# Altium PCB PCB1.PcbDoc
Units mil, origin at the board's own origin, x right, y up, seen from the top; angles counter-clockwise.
Board outline 6299.21 x 3937.01 mil, 4 copper layers (Top Layer, Top Inner, Bottom Inner, Bottom Layer), stack 60.709 mil thick; 67 components, 52 nets, 221 pads, 71 vias.
Unrouted connection lines stored in the file: 34.
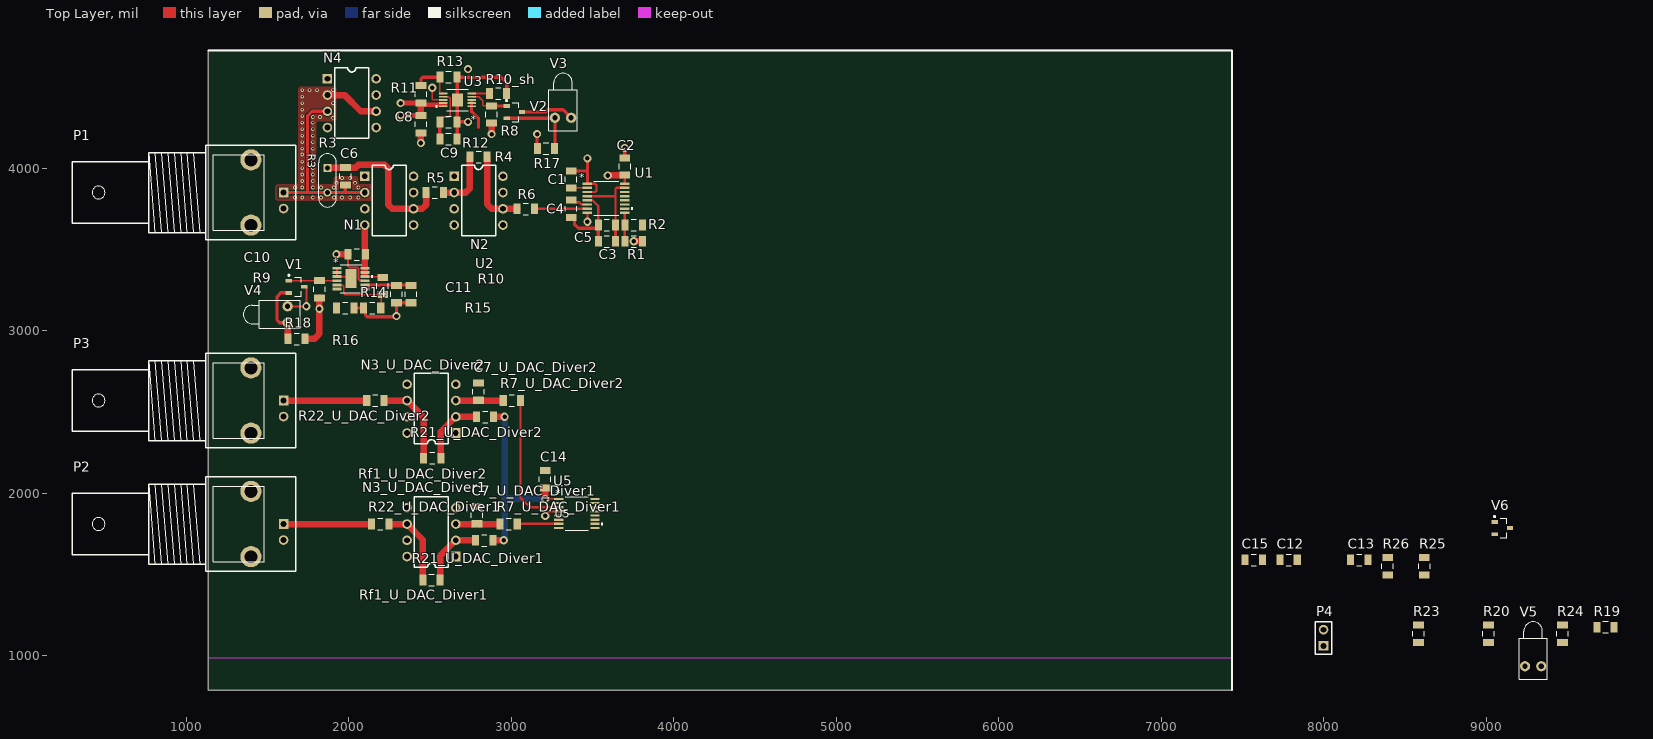
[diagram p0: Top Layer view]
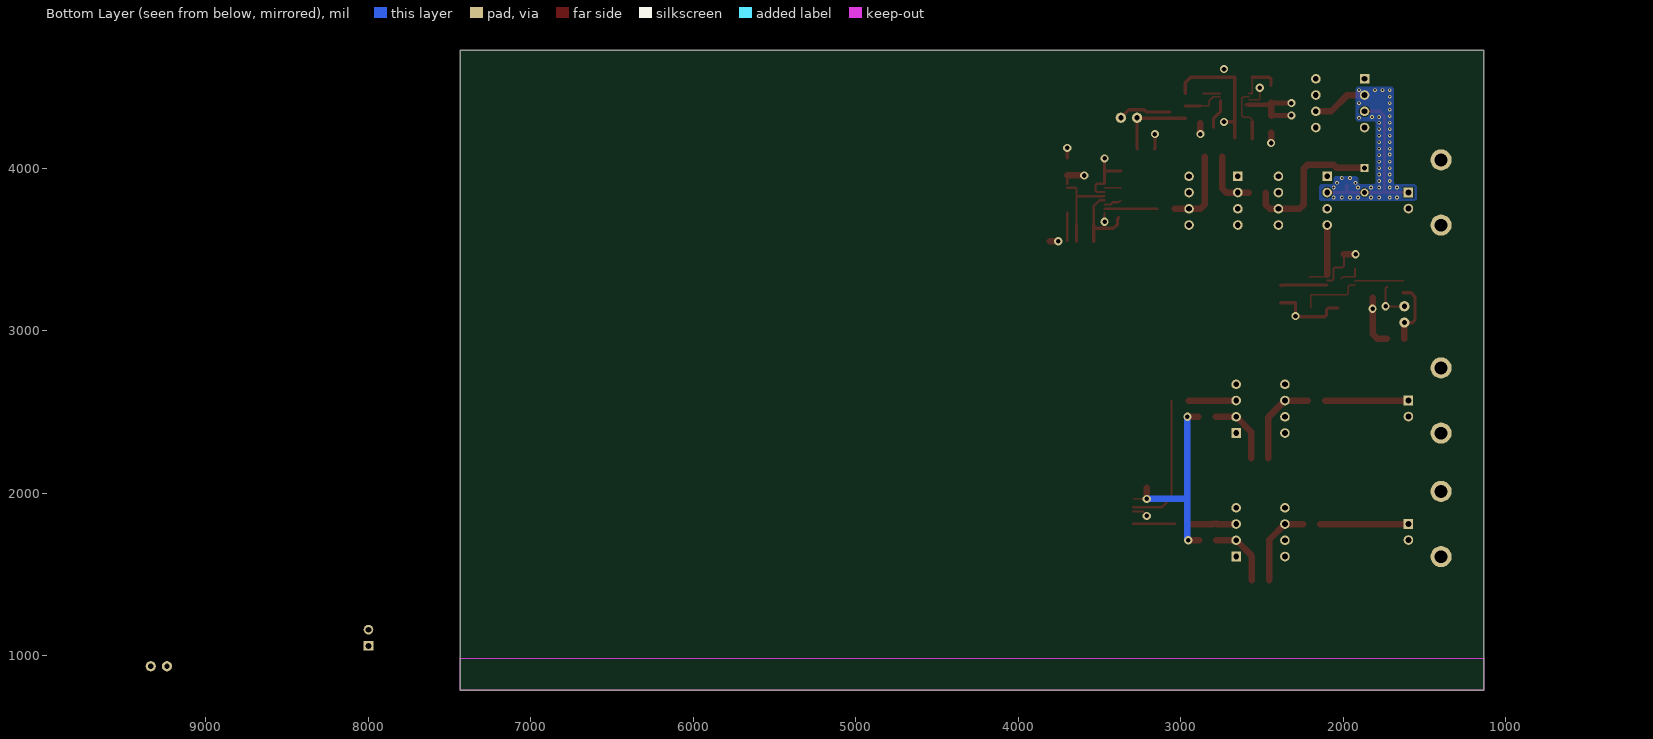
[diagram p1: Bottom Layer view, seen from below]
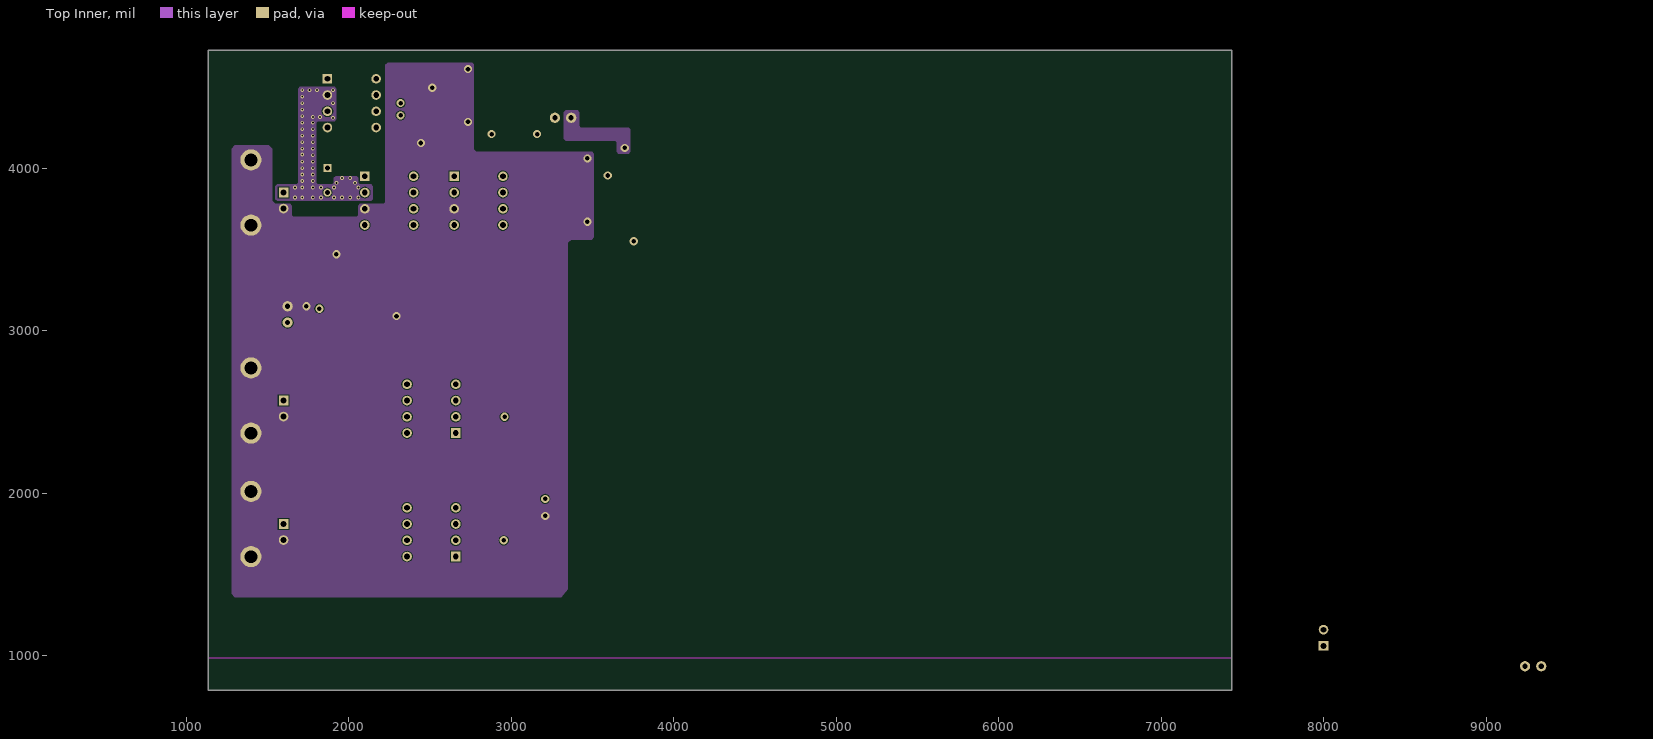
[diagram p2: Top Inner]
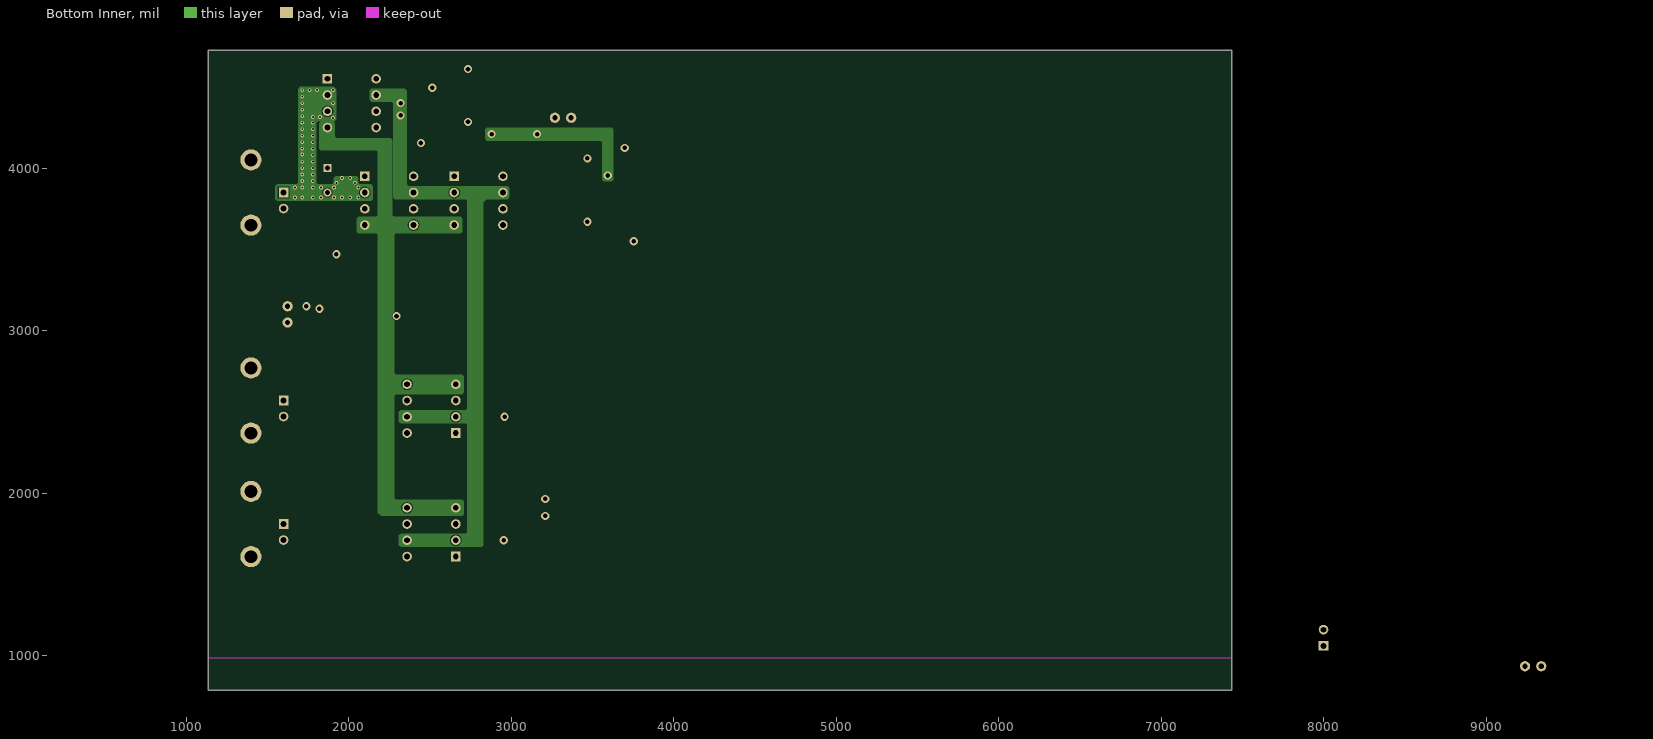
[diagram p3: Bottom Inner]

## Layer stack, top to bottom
Top Solder: solder mask 0.9843, Solder Resist, Dk 3.5
Top Layer: signal copper 1.378
Dielectric 1: prepreg 5.3543, PP-006, Dk 4.5
Top Inner: signal copper 1.378
Dielectric 2: dielectric 44.4882, FR-4, Dk 4.5
Bottom Inner: signal copper 1.378
Dielectric 3: prepreg 5.3543, PP-006, Dk 4.5
Bottom Layer: signal copper 1.378
Bottom Solder: solder mask 0.9843, Solder Resist, Dk 3.5

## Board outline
1137.4,787.4 7436.61,787.4 7436.61,4724.41 1137.4,4724.41

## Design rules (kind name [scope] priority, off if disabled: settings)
Clearance Clearance_1 [All] p1: gap=5 ignorepadtopadclearanceinfootprint=TRUE
Clearance [InNet('GUARD_RING') vs InNet('NetC6_1')] p2: gap=10 ignorepadtopadclearanceinfootprint=TRUE
DiffPairsRouting Diff_100_Ohms [All] p1: maxlimit=7 minlimit=5 mostfreqgap=6 toplayer_minwidth=13 toplayer_maxwidth=15 toplayer_prefwidth=14 midlayer1_minwidth=13 midlayer1_maxwidth=15 midlayer1_prefwidth=14 midlayer2_minwidth=13 midlayer2_maxwidth=15 midlayer2_prefwidth=14 bottomlayer_minwidth=13 bottomlayer_maxwidth=15 bottomlayer_prefwidth=14 maxuncoupledlength=50
HoleSize [All] p1: absolutevalues=TRUE maxlimit=137.8 minlimit=1 maxpercent=80.000 minpercent=20.000
PolygonConnect [All] p1: connectstyle=Direct reliefconductorwidth=10 reliefentries=4 polygonreliefangle="90 Angle" airgapwidth=10
RoutingVias [All] p1: holewidth=28 width=50 viastyle="Through Hole" minholewidth=11.81 minwidth=23.62 maxholewidth=28 maxwidth=50
SolderMaskExpansion [All] p1: expansion=4 istentingtop=FALSE
Width [All] p1: maxlimit=40 minlimit=10 preferedwidth=14
28 further rules are at their usual default settings.

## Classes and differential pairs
component class U_DAC: C12 C13 C14 C15 R25 R26 U5
channel class DAC_Diver: U_DAC_Diver1 U_DAC_Diver2
component class U_DAC_Diver2: C7_U_DAC_Diver2 N3_U_DAC_Diver2 R7_U_DAC_Diver2 R21_U_DAC_Diver2 R22_U_DAC_Diver2 Rf1_U_DAC_Diver2
component class U_DAC_Diver1: C7_U_DAC_Diver1 N3_U_DAC_Diver1 R7_U_DAC_Diver1 R21_U_DAC_Diver1 R22_U_DAC_Diver1 Rf1_U_DAC_Diver1
component class U_OPV_Psu: C8 C9 C10 C11 R8 R9 R10 R10_sh R11 R12 R13 R14 R15 R16 U2 U3 V1 V2
component class U_Source_OPV_ADC: C1 C2 C3 C4 C5 C6 N1 N2 N4 R1 R2 R3 R4 R5 R6 U1
component class TOP_Sheet: P1 P4 R17 R18 R19 R20 R23 R24 V3 V4 V5 V6

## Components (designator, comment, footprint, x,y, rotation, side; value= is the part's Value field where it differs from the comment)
C1 "0.1uF" C1206-KUE 3370,3930 r270 top
C2 "0.1uF" C1206-KUE 3700,4010 r270 top
C3 "10uF" C1206-KUE 3590,3550 r0 top
C4 "10uF" C1206-KUE 3370,3750 r90 top
C5 "100nF" C1206-KUE 3590,3650 r0 top
C6 "100nF" C1206-KUE 1980,3950 r90 top
C7_U_DAC_Diver1 "10uF" C1206-KUE 2790,1865 r270 top (schematic designator C7)
C7_U_DAC_Diver2 "10uF" C1206-KUE 2800,2625 r270 top (schematic designator C7)
C8 "10uF" C1206-KUE 2445,4270 r90 top
C9 "4.7uF" C1206-KUE 2615,4180 r180 top
C10 "10uF" C1206-KUE 2050,3470 r0 top
C11 "4.7uF" C1206-KUE 2385,3225 r90 top
C12 "0.1uF" C1206-KUE 7785,1590 r0 top
C13 "0.1uF" C1206-KUE 8220,1590 r0 top
C14 "0.1uF" C1206-KUE 3210,2085 r270 top
C15 "10uF" C1206-KUE 7570,1590 r0 top
N1 "UA741AN" DIP8 2250,3800 r270 top
N2 "UA741AN" DIP8 2800,3800 r270 top
N3_U_DAC_Diver1 "UA741AN" DIP8 2510,1760 r90 top (schematic designator N3)
N3_U_DAC_Diver2 "UA741AN" DIP8 2510,2520 r90 top (schematic designator N3)
N4 "UA741AN" DIP8 2020,4400 r270 top
P1 "BNC" "BNC_RA CON" 1600,3850 r0 top
P2 "BNC" "BNC_RA CON" 1600,1810 r0 top
P3 "BNC" "BNC_RA CON" 1600,2570 r0 top
P4 "Header 2" HDR1X2 8000,1060 r90 top
R1 "10k" C1206-KUE 3755,3550 r180 top
R2 "1k" C1206-KUE 3755,3650 r180 top
R3 "CNS020-10KP" RES_CNS020_VIS 1870,4000 r270 top
R4 "10k" C1206-KUE 2800,4070 r180 top
R5 "33k" C1206-KUE 2530,3850 r180 top
R6 "10" C1206-KUE 3090,3750 r180 top
R7_U_DAC_Diver1 "10k" C1206-KUE 2985,1810 r0 top (schematic designator R7)
R7_U_DAC_Diver2 "10k" C1206-KUE 3005,2570 r0 top (schematic designator R7)
R8 "10k" C1206-KUE 2880,4330 r90 top
R9 "10k" C1206-KUE 1820,3255 r90 top
R10 "255k" C1206-KUE 2210,3275 r270 top
R10_sh "0" C1206-KUE 2920,4460 r0 top
R11 "255k" C1206-KUE 2445,4455 r90 top
R12 "78.7k" C1206-KUE 2615,4285 r0 top
R13 "10k" C1206-KUE 2615,4560 r0 top
R14 "10k" C1206-KUE 2145,3140 r180 top
R15 "78.7k" C1206-KUE 2295,3225 r270 top
R16 "0" C1206-KUE 1980,3140 r0 top
R17 "2,2k" C1206-KUE 3215,4120 r0 top
R18 "2,2k" C1206-KUE 1680,2950 r180 top
R19 "2,2k" C1206-KUE 9735,1175 r0 top
R20 "10k" C1206-KUE 9015,1135 r90 top
R21_U_DAC_Diver1 "10k" C1206-KUE 2835,1710 r0 top (schematic designator R21)
R21_U_DAC_Diver2 "10k" C1206-KUE 2840,2470 r0 top (schematic designator R21)
R22_U_DAC_Diver1 "100" C1206-KUE 2195,1810 r0 top (schematic designator R22)
R22_U_DAC_Diver2 "100" C1206-KUE 2165,2570 r0 top (schematic designator R22)
R23 "10k" C1206-KUE 8585,1135 r90 top
R24 "10k" C1206-KUE 9470,1135 r90 top
R25 "10k" C1206-KUE 8620,1550 r90 top
R26 "10k" C1206-KUE 8395,1550 r90 top
Rf1_U_DAC_Diver1 "20k" C1206-KUE 2510,1465 r0 top (schematic designator Rf1)
Rf1_U_DAC_Diver2 "20k" C1206-KUE 2515,2215 r0 top (schematic designator Rf1)
U1 "ADS8681IPW" PW16_TEX 3585,3815 r0 top
U2 "LT3094EMSE#TRPBF" MSE_05-08-1666_ADI 2015,3320 r0 top
U3 "LT3042EMSE#TRPBF" 05-08-1664_ADI 2670,4420 r180 top
U5 "AD5689RBRUZ" RU_16_ADI 3405,1875 r0 top
V1 "BC847B" SOT23-KUE 1680,3270 r0 top
V2 "BC847B" SOT23-KUE 3020,4345 r0 top
V3 "LED1" LED-1 3320,4310 r90 top
V4 "LED1" LED-1 1625,3100 r180 top
V5 "LED1" LED-1 9290,935 r90 top
V6 "BC847B" SOT23-KUE 9100,1785 r0 top

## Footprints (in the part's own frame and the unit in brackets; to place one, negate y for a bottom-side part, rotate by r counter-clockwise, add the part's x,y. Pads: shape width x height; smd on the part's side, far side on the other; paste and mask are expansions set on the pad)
05-08-1664_ADI [mil]
  rect 52.28x11 smd paste+0 mask+0: 1(-87.14,39.37) 2(-87.14,19.69) 3(-87.14,0) 4(-87.14,-19.69) 5(-87.14,-39.37) 6(87.14,-39.37) 7(87.14,-19.69) 8(87.14,0) 9(87.14,19.69) 10(87.14,39.37)
  rect 70x78 smd paste+0 mask+0: 11(0,0)
  silkscreen extent -66,-66 133,66, body extent -99,-61 99,61, height 43
"BNC_RA CON" [mm] "Connector; BNC Elbow"
  rect 1.5x1.5 hole 0.9: 1(0,0)
  round 3.3 hole 2: 2(-5.1,-5.1) 2(-5.1,5.1)
  round 1.5 hole 0.9: 2(0,-2.5)
  silkscreen extent -33,-7.4 1.9,7.4
C1206-KUE [mm] "Chip Capacitor, Body 3.2x1.6mm, IPC High Density"
  rect 1.1x1.7 smd: 1(-1.35,0) 2(1.35,0)
  silkscreen extent -0.4,-0.9 0.4,0.9, body extent -1.6,-0.8 1.6,0.8, height 0.95
DIP8 [mm] "DIP; 8 Leads; Row Spacing 7.62 mm; Pitch 2.54 mm"
  rect 1.5x1.5 hole 0.9: 1(-3.81,-3.81)
  round 1.5 hole 0.9: 2(-1.27,-3.81) 3(1.27,-3.81) 4(3.81,-3.81) 5(3.81,3.81) 6(1.27,3.81) 7(-1.27,3.81) 8(-3.81,3.81)
  silkscreen extent -5.5,-2.65 5.5,2.65
HDR1X2 [mm] "Connector; Header; 2 Position"
  rect 1.5x1.5 hole 0.9: 1(0,0)
  round 1.5 hole 0.9: 2(2.54,0)
  silkscreen extent -1.27,-1.27 3.81,1.27
LED-1 [mm] "LED; 2 Leads"
  round 1.6 hole 0.8: 1(0,1.27) 2(0,-1.27)
  silkscreen extent -2,-2.2 6.95,2.2
MSE_05-08-1666_ADI [mil]
  rect 54.56x16.97 smd paste+0 mask+0: 1(-86,63.98) 2(-86,38.39) 3(-86,12.8) 4(-86,-12.8) 5(-86,-38.39) 6(-86,-63.98) 7(86,-63.98) 8(86,-38.39) 9(86,-12.8) 10(86,12.8) 11(86,38.39) 12(86,63.98)
  rect 69x116 smd paste-57.5 mask+0: 13(0,0)
  silkscreen extent -66,-86 133,86, body extent -99,-81 99,81, height 43
PW16_TEX [mil]
  rect 58x14 smd paste+0 mask+0: 1(-115,89.57) 2(-115,63.98) 3(-115,38.39) 4(-115,12.79) 5(-115,-12.8) 6(-115,-38.39) 7(-115,-63.98) 8(-115,-89.57) 9(115,-89.57) 10(115,-63.98) 11(115,-38.39) 12(115,-12.8) 13(115,12.79) 14(115,38.39) 15(115,63.98) 16(115,89.57)
  silkscreen extent -76,-105 164,106, body extent -130,-101 130,101, height 47
RES_CNS020_VIS [mil]
  rect 50x50 hole 30 paste-25 mask+0: 1(0,0)
  round 50 hole 30 paste-25 mask+0: 2(150,0)
  silkscreen extent -89,-55 239,55, body extent -84,-50 234,50, height 260
RU_16_ADI [mm]
  rect 1.461x0.351 smd paste+0 mask+0: 1(-2.825,2.275) 2(-2.825,1.625) 3(-2.825,0.975) 4(-2.825,0.325) 5(-2.825,-0.325) 6(-2.825,-0.975) 7(-2.825,-1.625) 8(-2.825,-2.275) 9(2.825,-2.275) 10(2.825,-1.625) 11(2.825,-0.975) 12(2.825,-0.325) 13(2.825,0.325) 14(2.825,0.975) 15(2.825,1.625) 16(2.825,2.275)
  silkscreen extent -1.81,-2.63 4.06,2.63, body extent -3.2,-2.5 3.2,2.5, height 1.2
SOT23-KUE [mm] "SOT23, 3-Leads, Body 2,90x2,45mm, Pitch 0,95mm, IPC Medium Density"
  rect 1x0.6 smd: 1(-1.2,0.95) 2(-1.2,-0.95) 3(1.2,0)
  silkscreen extent -1.32,-1.5 0.7,1.92, body extent -1.3,-1.5 1.3,1.5, height 1.1

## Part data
C1 C2 C3 C4 C5 C6 C7_U_DAC_Diver1 C7_U_DAC_Diver2 C8 C9 C10 C11 C12 C13 C14 C15: library part Capacitor, "Capacitor", Manufacturer=Kemet
N1 N2 N3_U_DAC_Diver1 N3_U_DAC_Diver2 N4: "General-Purpose Single Operational Amplifier"
P1 P2 P3: "BNC Elbow Connector"
P4: "Header, 2-Pin"
R1 R2 R4 R5 R6 R7_U_DAC_Diver1 R7_U_DAC_Diver2 R8 R9 R10 R10_sh R11 R12 R13 R14 R15 R16 R17 R18 R19 R20 R21_U_DAC_Diver1 R21_U_DAC_Diver2 R22_U_DAC_Diver1 R22_U_DAC_Diver2 R23 R24 R25 R26 Rf1_U_DAC_Diver1 Rf1_U_DAC_Diver2: library part ResistorSMD, "Resistor SMD", Manufacturer=AVX
R3: "CNS 020 10K 0,02% e2", Manufacturer_Name=Vishay
U1: "16-bit, 1MSPS 1-ch SAR ADC with programmable (Â±12V, Â±10V, Â±6V, Â±5V, Â±2.5V) input ranges on 5V supply 16-TSSOP -40 to 125", Manufacturer_Name="Texas Instruments"
U2: library part LT3094EMSETRPBF, "âˆ’20V, 500mA, Ultralow Noise, Ultrahigh PSRR Negative Linear Regulator", Manufacturer_Name="Analog Devices Inc"
U3: library part LT3042EMSETRPBF, "20V, 200mA, Ultralow Noise, Ultrahigh PSRR RF Linear Regulator", Manufacturer_Name="Analog Devices Inc"
U5: "Dual, 16-Bit nanoDAC+ with 2 ppm/Â°C Reference, SPI Interface", Manufacturer_Name="Analog Devices Inc"
V1 V2 V6: "NPN General-purpose Transistor SMD", Manufacturer=NXP
V3 V4 V5: "Typical RED GaAs LED"

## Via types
v1: diameter 23.62, hole 11.81, Top Layer to Bottom Layer, tented both sides, 50 vias
v2: diameter 50, hole 28, Top Layer to Bottom Layer, 21 vias

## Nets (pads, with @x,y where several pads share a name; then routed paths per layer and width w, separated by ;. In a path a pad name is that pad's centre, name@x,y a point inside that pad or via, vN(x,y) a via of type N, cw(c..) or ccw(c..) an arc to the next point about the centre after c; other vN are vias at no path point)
AGND: C1.1 C2.1 C7_U_DAC_Diver1.1 C7_U_DAC_Diver2.1 C8.1 C9.1 C10.1 C11.1 C12.1 C13.1 C14.1 C15.1 N1.3 N2.3 P1.2 P2.2 P3.2 R10_sh.2 R12.2 R13.2 R14.2 R15.2 R16.2 R25.2 R26.2 U1.1 U1.3 U1.8 U2.9 U3.8 U3.11 U5.4 V1.3 V2.3 V3.2 V4.2 V6.2 | length 3025.8
  Top Layer w10: v2(2515,4495) 2515,4425.86 2520.86,4420 U3.8 ; C9.1@2663.15,4185 C9.1 ; U3.11@2668.15,4420 U3.11 ; v2(3470,3670) U1.8
  Top Layer w12: V4.2 v2(1740,3150) 1740,3264.19 1734.19,3270 V1.3 ; C10.1 1997.32,3469.53 1997.32,3396.03 2004.35,3389 2054.06,3389 2061.61,3381.45 2061.61,3316.72 2068.64,3309.69 2098.52,3309.69 U2.9 ; v2(3210,1860) 3210,1861.77 3236.03,1887.8 U5.4
  Top Layer w14: U1.3 3517.23,3853.39 3525.43,3861.59 3525.43,3896.37 3517.23,3904.57 U1.1
  Top Layer w20: R16.2 R14.2 2103.5,3128.35 2103.5,3096.72 2115.22,3085 2280,3085 2295,3100 R15.2 C11.1 ; C9.1@2668.15,4185 R12.2 ; v2(2735,4285) R12.2 ; R10_sh.2 2973.15,4526.85 2940,4560 R13.2 2668.15,4420 R12.2 ; V2.3 3210,4345 3225,4360 3320,4360 V3.2 ; C1.1 3470,3983.15 ; U1.1@3470,3907.57 3470,3983.15 ; v2(3470,4060) 3470,3983.15 ; C2.1 v2(3700,4125)
  Top Layer w40: v2(1925,3470) C10.1 ; v2(2445,4155) C8.1
  other v2: 2295,3090 2735,4610
AVDD: C1.2 C12.2 C15.2 U1.2 U5.5 | length 100.9
  Top Layer w10: C1.2 3372.13,3878.98 U1.2
Digital33V: C2.2 C13.2 R1.1 R8.1 R9.1 R17.1 R18.1 R19.1 R23.1 R24.1 U1.16 U5.11 | length 689.9
  Top Layer w14: U1.16 C2.2
  Top Layer w20: v2(3160,4210) 3160,4121.85 R17.1
  Top Layer w40: R18.1 1734.52,2951.37 1791.37,2951.37 1820,2980 v2(1820,3135) R9.1 ; v2(2880,4210) R8.1 ; v2(3595,3955) 3596.85,3956.85 C2.2 ; v2(3755,3550) R1.1
GUARD_RING: N4.2 N4.6 | length 341.4
  Top Layer w40: N4.2 1975,4450 2075,4350 N4.6
  other v1: 1670,3820 1715,3820 1780,3820 1830,3820 1910,3820 1960,3820 2010,3820 2060,3820 1670,3880 1715,3880 1780,3880 1830,3880 1910,3880 2060,3880 1925,3910 2040,3910 1715,3920 1780,3920 1960,3940 2010,3940 1715,3960 1780,3960 1715,4000 1780,4000 1715,4040 1780,4040 1780,4080 1715,4085 1715,4120 1780,4120 1715,4160 1780,4160 1715,4200 1780,4200 1715,4240 1780,4240 1715,4280 1780,4280 1905,4310 1780,4315 1825,4315 1715,4320 1715,4360 1715,4400 1905,4400 1715,4440 1715,4480 1760,4480 1805,4480 1905,4480
neg_out: C10.2 N1.4 N2.4 N3_U_DAC_Diver1.4 N3_U_DAC_Diver2.4 N4.4 R10.1 U2.10 U2.11 U2.12 | length 555.3
  Top Layer w10: C10.2 2101,3467.85 U2.12 U2.11 2101,3345.59 U2.10 2205.35,3332.8 R10.1
  Top Layer w40: 2101,3345.59 2100,3346.59 N1.4 N1.4@2101.02,3648.98
NetC6_1: C6.1 N1.2 N4.3 P1.1 R3.2 | length 1145.1
  Top Layer w20: P1.1 R3.2 1980,3850 ; 1747.98,3857.98 1747.98,4322.98 1775,4350 N4.3 ; C6.1 1980,3850 ; N1.2 1980,3850
NetC6_2: C6.2 N1.6 R3.1 R5.2 | length 944
  Top Layer w40: R3.1 1873.15,4003.15 2043.15,4003.15 2060,4020 2221.57,4020 2245,3996.57 2245,3773.43 2268.43,3750 N1.6 2453.42,3750 2476.85,3773.43 R5.2
NetC7_U_DAC_Diver1_2: C7_U_DAC_Diver1.2 N3_U_DAC_Diver1.3 R7_U_DAC_Diver1.1 | length 273.4
  Top Layer w40: N3_U_DAC_Diver1.3 2776.34,1810 2778.19,1811.85 C7_U_DAC_Diver1.2 2801.81,1811.85 2803.66,1810 R7_U_DAC_Diver1.1
NetC7_U_DAC_Diver2_2: C7_U_DAC_Diver2.2 N3_U_DAC_Diver2.3 R7_U_DAC_Diver2.1 | length 291.9
  Top Layer w40: N3_U_DAC_Diver2.3 R7_U_DAC_Diver2.1
NetC9_2: C9.2 R12.1 U3.7 | length 342.9
  Top Layer w10: R12.1 2561.85,4296.51 2578.5,4313.17 2613.17,4313.17 2625,4325 2625,4430 2615,4440 2583.18,4440 U3.7
  Top Layer w20: C9.2 R12.1
NetC11_2: C11.2 R15.1 U2.8 | length 285.4
  Top Layer w20: U2.8 2381.54,3281.61 C11.2
NetC14_2: C14.2 R21_U_DAC_Diver1.2 R21_U_DAC_Diver2.2 U5.1 | length 1278.1
  Top Layer w10: v2(3210,1965) 3210.43,1964.57 U5.1
  Top Layer w40: R21_U_DAC_Diver1.2 v2(2955,1710) ; R21_U_DAC_Diver2.2 v2(2960,2470) ; v2(3210,1965) C14.2
  Bottom Layer w40: v2(2955,1710) 2955,1712.71 2960,1717.71 v2(2960,2470) ; 2978.43,1965 v2(3210,1965)
NetN2_2: N2.2 R4.2 R5.1 | length 363
  Top Layer w40: R5.1@2588.15,3850 N2.2 2720,3850 2746.85,3876.85 R4.2
NetN2_6: N2.6 R4.1 R6.2 | length 488
  Top Layer w40: R4.1 2853.15,3776.85 2880,3750 N2.6 R6.2
NetN3_U_DAC_Diver1_2: N3_U_DAC_Diver1.2 R21_U_DAC_Diver1.1 Rf1_U_DAC_Diver1.2 | length 407
  Top Layer w40: Rf1_U_DAC_Diver1.2 2563.15,1613.15 N3_U_DAC_Diver1.2 R21_U_DAC_Diver1.1
NetN3_U_DAC_Diver1_6: N3_U_DAC_Diver1.6 R22_U_DAC_Diver1.2 Rf1_U_DAC_Diver1.1 | length 497
  Top Layer w40: R22_U_DAC_Diver1.2 N3_U_DAC_Diver1.6 2456.85,1713.15 Rf1_U_DAC_Diver1.1
NetN3_U_DAC_Diver2_2: N3_U_DAC_Diver2.2 R21_U_DAC_Diver2.1 Rf1_U_DAC_Diver2.2 | length 419.9
  Top Layer w40: Rf1_U_DAC_Diver2.2 2568.15,2378.15 N3_U_DAC_Diver2.2 R21_U_DAC_Diver2.1
NetN3_U_DAC_Diver2_6: N3_U_DAC_Diver2.6 R22_U_DAC_Diver2.2 Rf1_U_DAC_Diver2.1 | length 539
  Top Layer w40: R22_U_DAC_Diver2.2 N3_U_DAC_Diver2.6 2461.85,2468.15 Rf1_U_DAC_Diver2.1
NetP2_1: P2.1 R22_U_DAC_Diver1.1 | length 541.9
  Top Layer w40: P2.1 R22_U_DAC_Diver1.1
NetP3_1: P3.1 R22_U_DAC_Diver2.1 | length 511.9
  Top Layer w40: P3.1 R22_U_DAC_Diver2.1
NetP4_1: P4.1 U2.1 U2.2 U2.3 U2.13 | length 142.5
  Top Layer w10: U2.1 U2.2 U2.3 2002.2,3332.8 U2.13
NetP4_2: P4.2 U3.1 U3.2 U3.3 | length 182.8
  Top Layer w20: U3.3@2757.14,4415 U3.2 U3.1 2757.14,4347.86 2800,4305 2800,4250
NetR1_2: R1.2 R2.2 U1.9 | length 173.6
  Top Layer w14: R1.2@3700,3551.85 U1.9
NetR2_1: R2.1 R24.2
NetR7_U_DAC_Diver1_2: R7_U_DAC_Diver1.2 U5.7 | length 256.7
  Top Layer w10: R7_U_DAC_Diver1.2@3038.58,1809.57 R7_U_DAC_Diver1.2 R7_U_DAC_Diver1.2@3039.17,1811.02
  Top Layer w15: R7_U_DAC_Diver1.2@3039.17,1811.02 U5.7
NetR7_U_DAC_Diver2_2: R7_U_DAC_Diver2.2 U5.3 | length 863.6
  Top Layer w10: R7_U_DAC_Diver2.2 R7_U_DAC_Diver2.2@3062.09,2566.05
  Top Layer w15: R7_U_DAC_Diver2.2 3058.15,1971.85 3116.61,1913.39 U5.3
NetR8_2: R8.2 U3.4 V2.1 | length 252.4
  Top Layer w10: U3.4 2800.32,4439.69 2825,4415 2825,4390.86 2830.86,4385 2878.15,4385 R8.2
  Top Layer w20: R8.2@2880.75,4382.4 V2.1
NetR9_2: R9.2 U2.4 V1.1 | length 296.3
  Top Layer w10: V1.1 1632.95,3307.2 U2.4
NetR10_2: R10.2 R14.1 U2.5 | length 403.4
  Top Layer w10: U2.5 1931.46,3279.15 1963.51,3279.15 1969.37,3273.29 1969.37,3230.63 1978.15,3221.85 2200,3221.85 2200,3141.85 R14.1
NetR10_sh_1: R10_sh.1 U3.5 | length 109.1
  Top Layer w10: U3.5 R10_sh.1@2866.22,4459.37
NetR11_2: R11.2 R13.1 U3.6 | length 283.2
  Top Layer w10: R13.1 2561.85,4459.87 2562.35,4459.37 U3.6
  Top Layer w20: R11.2 2445,4548.28 2456.72,4560 R13.1
NetR16_1: R16.1 U2.6
NetR17_2: R17.2 V2.2 V3.1 | length 489.1
  Top Layer w20: V2.2 3267.4,4307.6 V3.1@3270,4305 ; R17.2 3270,4121.85 V3.1@3270,4305 ; V3.1 V3.1@3270,4305
NetR18_2: R18.2 V1.2 V4.1 | length 400.4
  Top Layer w20: V4.1 1623.48,3048.48 1576.52,3048.48 1560,3065 1560,3210 1582.6,3232.6 V1.2
  Top Layer w40: V4.1 1625,2963.66 1626.85,2961.81 R18.2
NetR19_2: R19.2 V5.1
NetR20_1: R20.1 U1.14
NetR20_2: R20.2 V6.1
NetR23_2: R23.2 U5.15
NetR25_1: R25.1 U5.16
NetR26_1: R26.1 U5.9
NetU1_10: U1.10 U5.14
NetU1_11: U1.11
NetU1_12: U1.12 U5.12
NetU1_13: U1.13 U5.8
NetU5_10: U5.10
NetU5_13: U5.13
NetV5_2: V5.2 V6.3
pos_out: C8.2 N1.7 N2.7 N3_U_DAC_Diver1.7 N3_U_DAC_Diver2.7 N4.7 R11.1 U3.9 U3.10 | length 490.2
  Top Layer w20: 2582.86,4390.47 2600,4390.47
  Top Layer w30: v2(2320,4325) 2443.15,4325 C8.2 ; v2(2320,4400) 2443.15,4400 R11.1 ; R11.1@2440,4390.47 2445,4390.47 2582.86,4390.47
  Top Layer w40: C8.2 2445,4390.47 R11.1
REFCAP: C4.2 U1.6 | length 106
  Top Layer w10: C4.2 C4.2@3383.15,3790 ; U1.6@3469.7,3776.91 U1.6
  Top Layer w14: C4.2@3388.15,3790 3420,3790 3433.09,3776.91 U1.6@3469.7,3776.91
REFGND: C3.1 C4.1 C5.1 U1.5 | length 492.7
  Top Layer w14: U1.5 3501.62,3802.2 3536.85,3766.98 C5.1
  Top Layer w20: C4.1@3381.81,3696.85 3390,3688.66 3390,3655 3415,3630 3536.85,3630 C3.1 ; C5.1@3536.85,3638.19 C5.1
REFIO: C3.2 C5.2 U1.4 U1.15 | length 552.8
  Top Layer w14: U1.4 3640.36,3827.79 ; C5.2 3643.15,3873.12 3649.01,3878.98 U1.15
  Top Layer w20: C3.2 C5.2
TIA_OUT: R6.1 U1.7 | length 325.8
  Top Layer w14: R6.1@3144.17,3751.02 U1.7
pads on no net: N1.1 N1.5 N1.8 N2.1 N2.5 N2.8 N3_U_DAC_Diver1.1 N3_U_DAC_Diver1.5 N3_U_DAC_Diver1.8 N3_U_DAC_Diver2.1 N3_U_DAC_Diver2.5 N3_U_DAC_Diver2.8 N4.1 N4.5 N4.8 U2.7 U5.2 U5.6

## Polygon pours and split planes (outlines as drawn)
GUARD_RING on Top Layer "GUARD_RING_L01_P020" (solid, pour order 20): 1690,4490 1700,4500 1915,4500 1925,4490 1925,4300 1915,4290 1810,4290 1800,4280 1800,3910 1810,3900 1900,3900 1910,3910 1910,3940 1920,3950 2050,3950 2060,3940 2060,3910 2070,3900 2140,3900 2150,3890 2150,3810 2140,3800 1560,3800 1550,3810 1550,3890 1560,3900 1680,3900 1690,3910
AGND on Top Inner (solid, pour order 30): 1280,3005 1280,1380 1300,1360 3310,1360 3350,1410 3350,3540 3370,3560 3495,3560 3510,3575 3510,4090 3500,4100 3440,4100 2785,4100 2770,4115 2770,4640 2760,4650 2240,4650 2225,4635 2225,4305 2225,3790 2215,3780 2070,3780 2060,3770 2060,3710 2050,3700 1660,3700 1650,3710 1650,3770 1640,3780 1550,3780 1530,3800 1530,4120 1510,4140 1300,4140 1280,4120 1280,3580
AGND on Top Inner "AGND_L02_P028" (solid, pour order 28): 3660,4090 3650,4100 3650,4160 3640,4170 3335,4170 3325,4180 3325,4345 3335,4355 3410,4355 3420,4345 3420,4260 3430,4250 3725,4250 3735,4240 3735,4100 3725,4090
GUARD_RING on Top Inner "GUARD_RING_L02_P021" (solid, pour order 21): 1690,4490 1700,4500 1915,4500 1925,4490 1925,4300 1915,4290 1810,4290 1800,4280 1800,3910 1810,3900 1900,3900 1910,3910 1910,3940 1920,3950 2050,3950 2060,3940 2060,3910 2070,3900 2140,3900 2150,3890 2150,3810 2140,3800 1560,3800 1550,3810 1550,3890 1560,3900 1680,3900 1690,3910
Digital33V on Bottom Inner "DIGITAL33V_L03_P029" (solid, pour order 29): 2840,4240 2850,4250 3620,4250 3630,4240 3630,3930 3620,3920 3570,3920 3560,3930 3560,4160 3550,4170 2850,4170 2840,4180
GUARD_RING on Bottom Inner "GUARD_RING_L03_P027" (solid, pour order 27): 1910,4500 1920,4490 1925,4490 1925,4300 1915,4290 1810,4290 1800,4280 1800,3910 1810,3900 1900,3900 1910,3910 1910,3940 1920,3950 2050,3950 2060,3940 2060,3910 2070,3900 2140,3900 2150,3890 2150,3810 2140,3800 1560,3800 1550,3810 1550,3890 1560,3900 1680,3900 1690,3910 1690,4490 1700,4500 1915,4500 1925,4490
pos_out on Bottom Inner "Bottom Inner-pos_out" (solid, pour order 17): 2720,3810 2730,3800 2730,2520 2720,2510 2320,2510 2310,2500 2310,2440 2320,2430 2720,2430 2730,2420 2730,1760 2720,1750 2320,1750 2310,1740 2310,1680 2320,1670 2820,1670 2830,1680 2830,3790 2850,3810 2980,3810 2990,3820 2990,3880 2980,3890 2370,3890 2357.5,3902.5 2357.5,4477.5 2345,4490 2140,4490 2130,4480 2130,4420 2140,4410 2265,4410 2275,4400 2275,3880 2275,3820 2285,3810 2430,3810
neg_out on Bottom Inner "NONET_L-01_P-001" (solid, pour order 15): 2280,2740 2290,2730 2700,2730 2710,2720 2710,2620 2700,2610 2290,2610 2280,2600 2280,1970 2290,1960 2700,1960 2710,1950 2710,1870 2700,1860 2200,1860 2180,1880 2180,3590 2170,3600 2060,3600 2050,3610 2050,3690 2060,3700 2170,3700 2180,3710 2180,4100 2170,4110 1830,4110 1820,4120 1820,4275 1830,4285 1905,4285 1915,4275 1915,4195 1925,4185 2260,4185 2270,4175 2270,3710 2280,3700 2690,3700 2700,3690 2700,3610 2690,3600 2290,3600 2280,3590
no net on Top Solder "NONET_L-01_P-001" (solid): 1700,4485 1705,4490 1910,4490 1915,4485 1915,4310 1905,4300 1800,4300 1790,4290 1790,3900 1800,3890 1910,3890 1920,3900 1920,3930 1930,3940 2040,3940 2050,3930 2050,3900 2060,3890 2130,3890 2140,3880 2140,3820 2130,3810 1570,3810 1560,3820 1560,3880 1570,3890 1690,3890 1700,3900
GUARD_RING on Bottom Layer "GUARD_RING_L04_P023" (solid, pour order 23): 1690,4490 1700,4500 1915,4500 1925,4490 1925,4300 1915,4290 1810,4290 1800,4280 1800,3910 1810,3900 1900,3900 1910,3910 1910,3940 1920,3950 2050,3950 2060,3940 2060,3910 2070,3900 2140,3900 2150,3890 2150,3810 2140,3800 1560,3800 1550,3810 1550,3890 1560,3900 1680,3900 1690,3910

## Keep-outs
Keep-Out Layer:
  rectangle: 1137.4,787.4 7436.61,984.25

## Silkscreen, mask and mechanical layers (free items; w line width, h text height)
Top Overlay:
  lines w10: 7436.61,787.4 7436.61,4724.41
  lines w10.08: 1137.4,4724.41 7436.61,4724.41
Mechanical 4:
  lines w10: 1137.4,4724.41 1137.4,787.4 7436.61,787.4

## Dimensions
1137.4,787.4 to 7436.61,4724.41 on Mechanical 4
1137.4,787.4 to 1137.4,4724.41 on Mechanical 4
